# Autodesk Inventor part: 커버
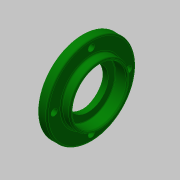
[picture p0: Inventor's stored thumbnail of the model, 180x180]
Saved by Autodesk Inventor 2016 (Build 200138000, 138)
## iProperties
Created: 2018-11
Part Number: 커버
Material: 알루미늄 6061
Document SubType Name: Modeling
Designer: mduedu
Density: 1 g/cm^3
Appearance: 진녹색
Author: mduedu
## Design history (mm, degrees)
sketch "스케치1"
  geometry: L1 (0, 0)-(2, 0); L2 (2, 0)-(2, 20); L3 (2, 20)-(0, 20); L4 (0, 20)-(0, 0); L5 (2, 0)-(8, 0); L6 (8, 0)-(8, 31); L7 (8, 31)-(2, 31); L8 (2, 31)-(2, 0); L9 (8, 0)-(14, 0); L10 (14, 0)-(14, 21); L11 (14, 21)-(8, 21); L12 (8, 21)-(8, 0)
  constraints: 24 end point, 6 parallel, 3 horizontal, 3 perpendicular
  dimensions: "d0" = 62 diameter of L7 L5; "d2" = 42 diameter of L11 L9; "d3" = 40 diameter of L3 L1; "d4" = 2 distance of L2.end L3.end; "d5" = 6 distance of L6.end L7.end; "d6" = 14 distance between parallel lines of L10 L4
revolve "회전1" sketch "스케치1" stored, may be unused: angle "d7" = 90 deg
sketch "스케치2"
  geometry: L1 (0, -20)-(0, 20) reference; L2 (0, 20)-(2, 20) reference; L3 (2, 20)-(2, 31) reference; L4 (2, 31)-(8, 31) reference; L5 (8, 31)-(8, 21) reference; L6 (8, 21)-(14, 21) reference; L7 (14, 21)-(14, -21) reference; L8 (14, -21)-(8, -21) reference; L9 (8, -21)-(8, -31) reference; L10 (8, -31)-(2, -31) reference; L11 (2, -31)-(2, -20) reference; L12 (2, -20)-(0, -20) reference; L13 (0, 0)-(2, 0); L14 (2, 0)-(2, 16.5); L15 (2, 16.5)-(0, 16.5); L16 (0, 16.5)-(0, 0); L17 (2, 0)-(5.7, 0); L18 (5.7, 0)-(5.7, 14); L19 (5.7, 14)-(2, 14); L20 (2, 14)-(2, 0); L21 (5.7, 0)-(14, 0); L22 (14, 0)-(14, 19); L23 (14, 19)-(5.7, 19); L24 (5.7, 19)-(5.7, 0)
  constraints: 24 end point, 6 parallel, 3 horizontal, 3 perpendicular, 1 point on line
  dimensions: "d8" = 38 diameter of L23 L21; "d10" = 28 diameter of L19 L17; "d11" = 33 diameter of L15 L13; "d12" = 2 distance of L14.end L15.end; "d13" = 8.3 distance of L22.end L23.end
revolve "회전2" sketch "스케치2" stored, may be unused: angle "d14" = 90 deg
fillet "모깎기1" dims "d15" = 0.3
chamfer "모따기1" distance "d16" = 0.8; stored, may be unused: second distance "d17" = 2, angle "d18" = 30 deg
fillet "모깎기2" dims "d19" = 1
chamfer "모따기2" distance "d20" = 0.5; stored, may be unused: second distance "d21" = 2, angle "d22" = 30 deg
sketch "스케치3" dims "d23" = 52
  geometry: 6 further points
  constraints: 2 vertical alignment, 1 coincident, 7 other
  dimensions: "d26" = 360 deg dimension on point (0, 0) point (0, 26) (derived)
sketch "스케치4"
  geometry: 4 further points
  constraints: 4 other
hole "구멍1" sketch "스케치4" at (-26, 0), (0, -26), (26, 0), (0, 26) diameter "d28" = 4.5; stored, may be unused: countersink angle "d32" = 90 deg, drill point angle "d34" = 0 deg; dims "d29" = 6, "d30" = 8, "d31" = 4.6, "d33" = 8
node "솔리드1"
node "절단 모서리 투영1"
